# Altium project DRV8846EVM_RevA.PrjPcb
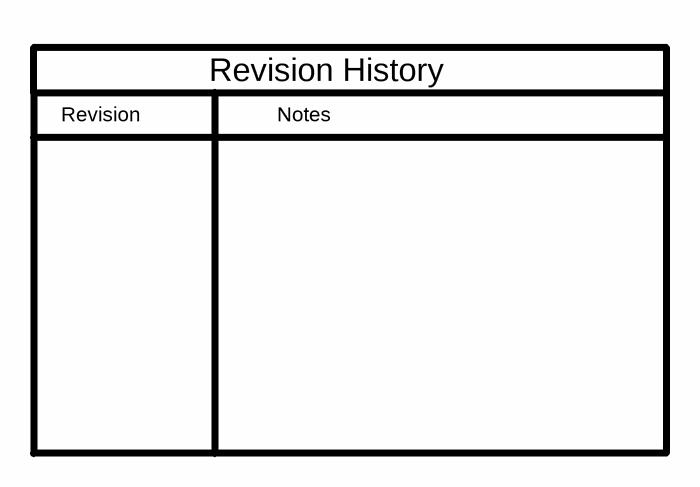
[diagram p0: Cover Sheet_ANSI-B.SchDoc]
TechSupport: http://www.ti.com/support; SCH_Rev: A; PRJ_Title: DRV8846EVM; PRJ_Number: DRV8846EVM; PRJ_Engineer: Rick Duncan; PRJ_Customer: Public Release; PCB_Rev: Rev A; PCB_Layout: Rick Duncan; CopyrightYear: 2014
4 sheets, 52 parts. Net scope: global (net labels, ports and power ports of the same name join across sheets).
Board file: DRV8846EVM_RevA.PcbDoc
Sheets:
  Cover Sheet_ANSI-B.SchDoc
  DRV8846EVM_RevA.SchDoc
  Hardware_ANSI-B.SchDoc
  DRV8846EVM_MSP430F2617_RevA.SchDoc

## Sheet Cover Sheet_ANSI-B.SchDoc
size 431 x 279 mm; Date: Not shown in title block; ApprovedBy: Not shown in title block; CheckedBy: Not shown in title block; Author: Not shown in title block; CompanyName: Not shown in title block; Engineer: Not shown in title block; Organization: Not shown in title block; Address1: Not shown in title block; Address2: Not shown in title block; Address3: Not shown in title block; Address4: Not shown in title block; DocumentNumber: 1; Revision: Use project parameter SCH_Rev; SheetNumber: 1; SheetTotal: 1; PageSetup: Record=PageOptions|CenterHorizontal=True|CenterVertical=True|PrintScale=1.00|XCorrection=1.00|YCorrection=1.00|PrintKind=0|BorderSize=5000000|LeftOffset=0|BottomOffset=0|Orientation=2|PaperLength=1000|PaperWidth=1000|Scale=100|PaperSource=15|PrintQuality=600|MediaType=1|DitherType=10|PaperKind=Letter|PrintScaleMode=1

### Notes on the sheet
- Revision
- Notes
- Revision History

## Sheet DRV8846EVM_RevA.SchDoc
size 431 x 279 mm; Date: Not shown in title block; ApprovedBy: Not shown in title block; CheckedBy: Not shown in title block; Author: Not shown in title block; CompanyName: Not shown in title block; Engineer: Not shown in title block; Organization: Not shown in title block; Address1: Not shown in title block; Address2: Not shown in title block; Address3: Not shown in title block; Address4: Not shown in title block; DocumentNumber: 1; Revision: Use project parameter SCH_Rev; SheetNumber: 1; SheetTotal: 1; PageSetup: Record=PageOptions|CenterHorizontal=True|CenterVertical=True|PrintScale=1.00|XCorrection=1.00|YCorrection=1.00|PrintKind=0|BorderSize=5000000|LeftOffset=0|BottomOffset=0|Orientation=2|PaperLength=1000|PaperWidth=1000|Scale=100|PaperSource=15|PrintQuality=600|MediaType=1|DitherType=10|PaperKind=Letter|PrintScaleMode=1
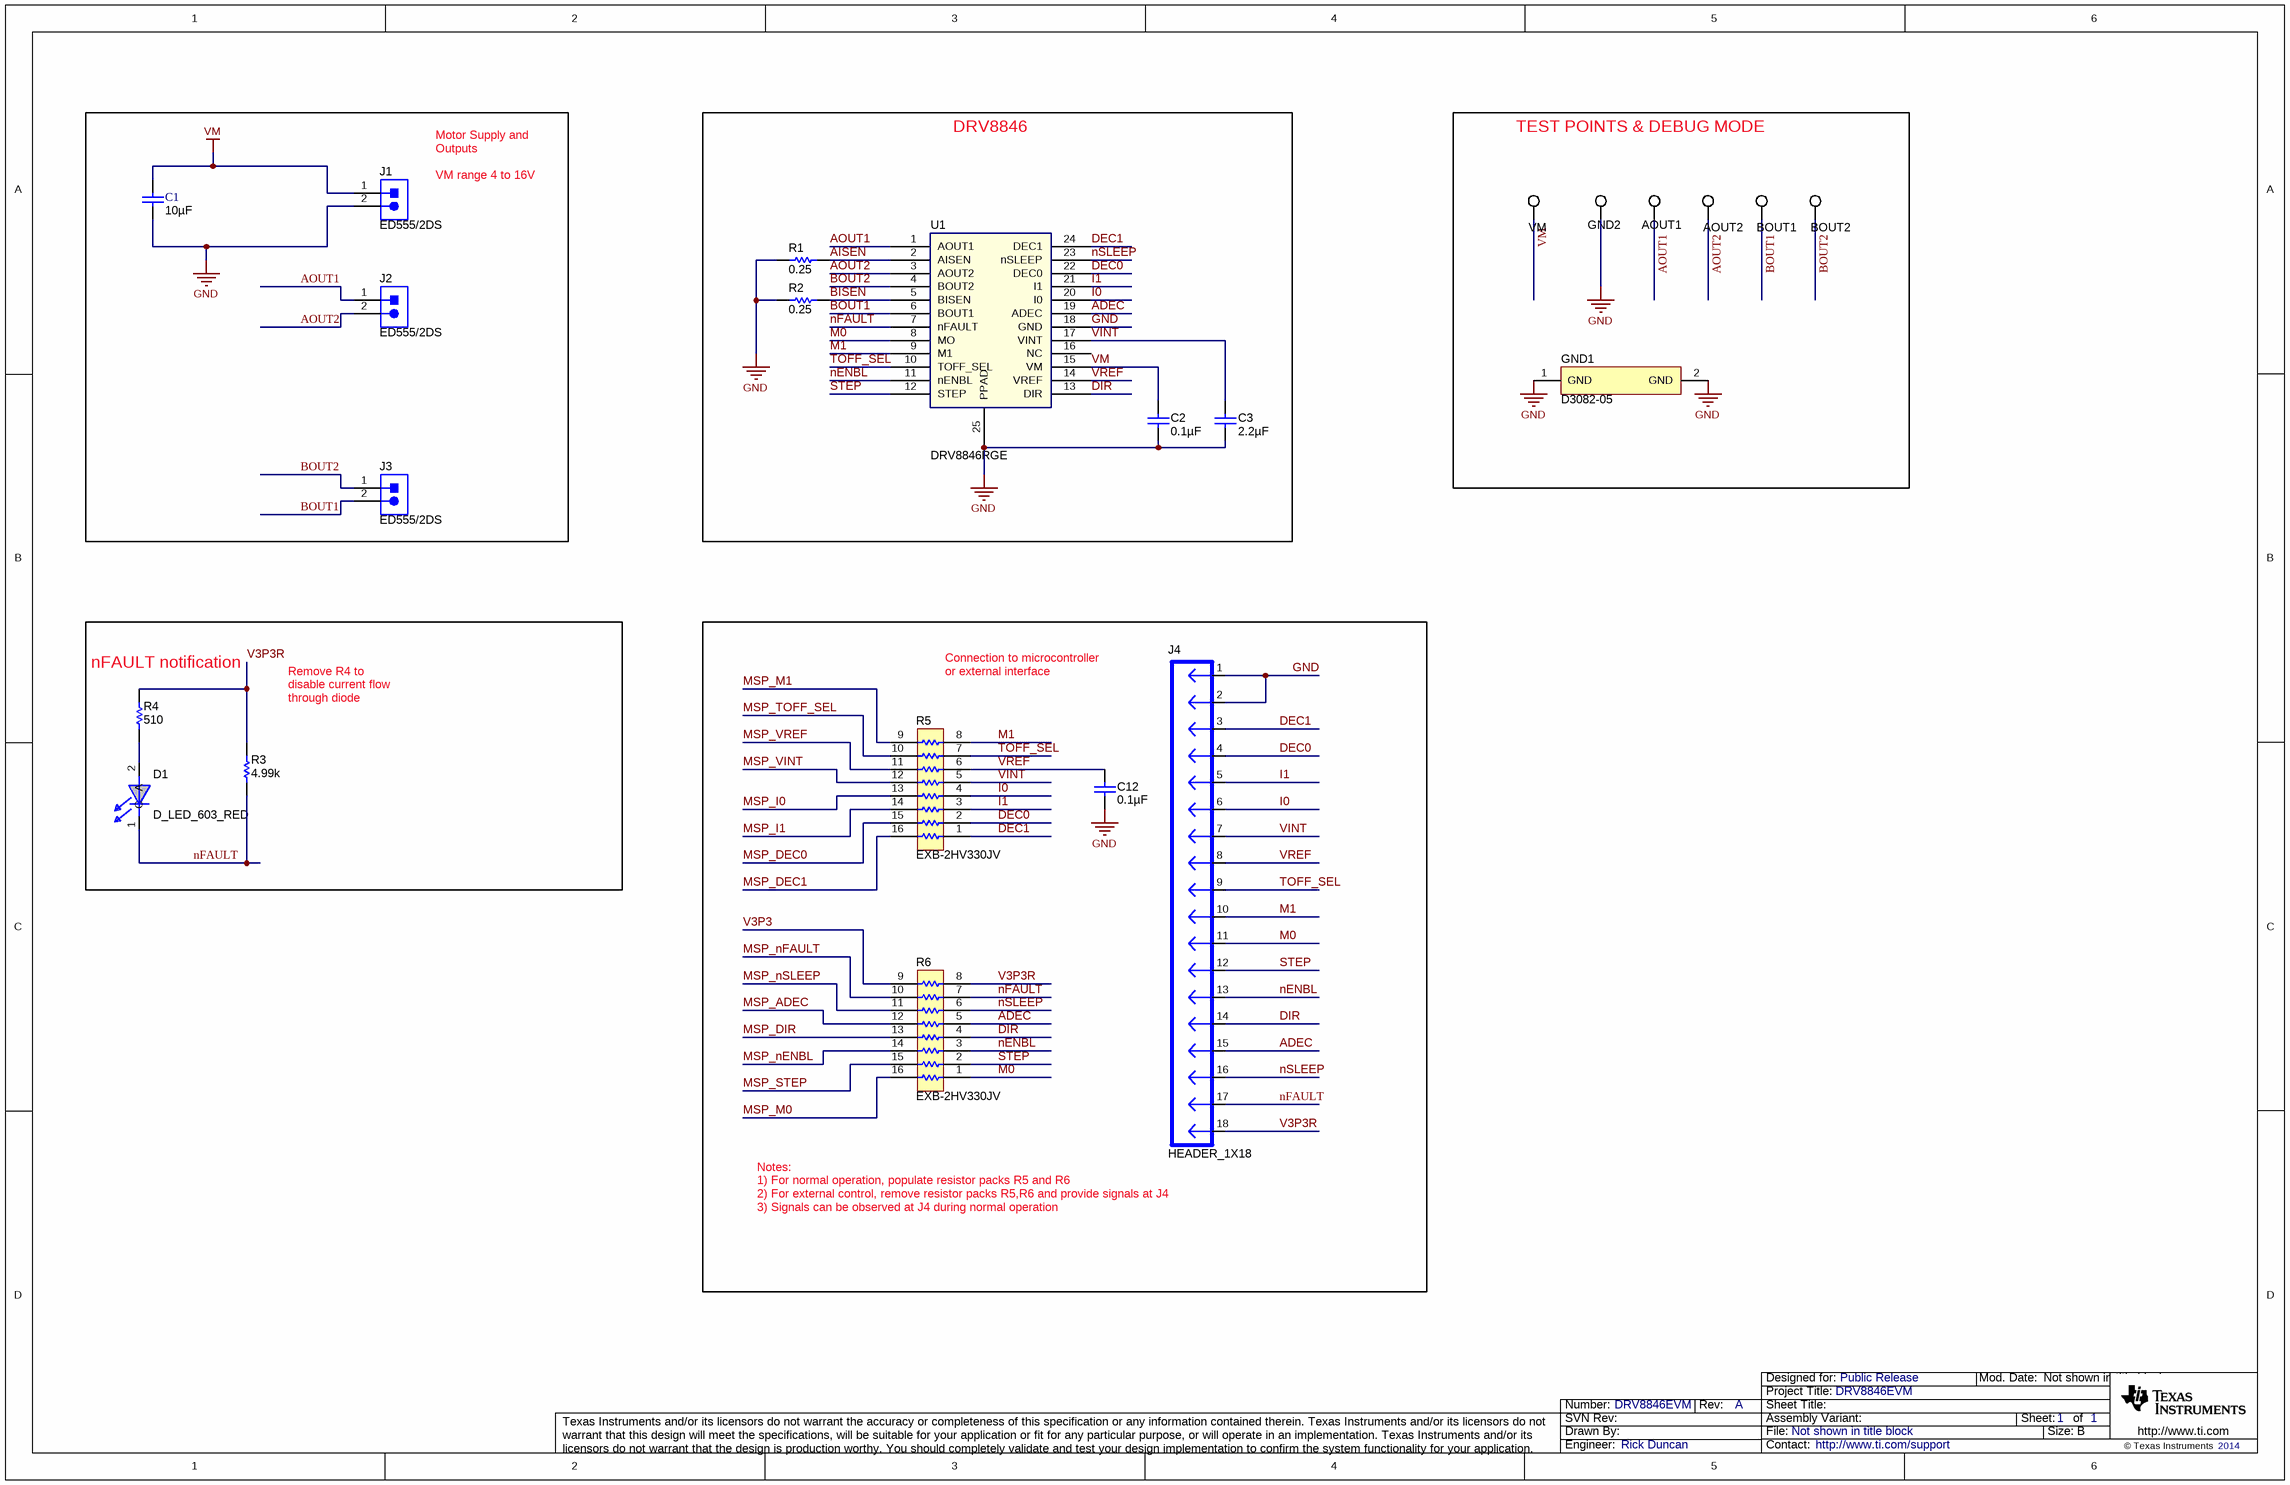
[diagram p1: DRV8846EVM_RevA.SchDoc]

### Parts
AOUT1  5016  [Testpoint_Keystone_Compact]  (value not drawn)
AOUT2  5016  [Testpoint_Keystone_Compact]  (value not drawn)
BOUT1  5016  [Testpoint_Keystone_Compact]  (value not drawn)
BOUT2  5016  [Testpoint_Keystone_Compact]  (value not drawn)
C1  ValueDisplayed: 10µF  [1210L]  (hidden comment: GMK325AB7106MM-T)
C2  ValueDisplayed: 0.1µF  [0603L]  (hidden comment: 06035C104KAT2A)
C3  ValueDisplayed: 2.2µF  [0402L]  (hidden comment: C1005X5R1E225K050BC)
C12  ValueDisplayed: 0.1µF  [0402L]  (hidden comment: C1005X5R0J104K)
D1  D_LED_603_RED  [LED603]
GND1  D3082-05  [GND_BRIDGE]
GND2  5016  [Testpoint_Keystone_Compact]  (value not drawn)
J1  ED555/2DS  [TERM_BLK_ED555-2DS]
J2  ED555/2DS  [TERM_BLK_ED555-2DS]
J3  ED555/2DS  [TERM_BLK_ED555-2DS]
J4  HEADER_1X18  [HEADER_1X18]
R1  value 0.25  [2010L]  (hidden comment: CSRN2010FKR250)
R2  value 0.25  [2010L]  (hidden comment: CSRN2010FKR250)
R3  value 4.99k  [0402L]  (hidden comment: CRCW04024K99FKED)
R4  value 510  [0402L]  (hidden comment: CRCW0402510RJNED)
R5  EXB-2HV330JV  [RESCAXS_EXB-2HV]
R6  EXB-2HV330JV  [RESCAXS_EXB-2HV]
U1  DRV8846RGE  [RGE0024H_MDBU]
VM  5016  [Testpoint_Keystone_Compact]  (value not drawn)

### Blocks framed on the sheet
DRV8846: C2 C3 R1 R2 U1
TEST POINTS & DEBUG MODE: AOUT1 AOUT2 BOUT1 BOUT2 GND1 GND2 VM
nFAULT notification: D1 R3 R4

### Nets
GND: C1.2 C2.2 C3.2 C12.2 GND1.1(GND) GND1.2(GND) GND2.1 J1.2 J4.1 J4.2 R1.1 R2.1 U1.18(GND) U1.25(PPAD)
V3P3: R6.9
VM: C1.1 C2.1 J1.1 U1.15(VM) VM.1
ADEC: J4.15 R6.5 U1.19(ADEC)
AISEN: R1.2 U1.2(AISEN)
AOUT1: AOUT1.1 J2.1 U1.1(AOUT1)
AOUT2: AOUT2.1 J2.2 U1.3(AOUT2)
BISEN: R2.2 U1.5(BISEN)
BOUT1: BOUT1.1 J3.2 U1.6(BOUT1)
BOUT2: BOUT2.1 J3.1 U1.4(BOUT2)
DEC0: J4.4 R5.2 U1.22(DEC0)
DEC1: J4.3 R5.1 U1.24(DEC1)
DIR: J4.14 R6.4 U1.13(DIR)
I0: J4.6 R5.4 U1.20(I0)
I1: J4.5 R5.3 U1.21(I1)
M0: J4.11 R6.1 U1.8(MO)
M1: J4.10 R5.8 U1.9(M1)
MSP_ADEC: R6.12
MSP_DEC0: R5.15
MSP_DEC1: R5.16
MSP_DIR: R6.13
MSP_I0: R5.13
MSP_I1: R5.14
MSP_M0: R6.16
MSP_M1: R5.9
MSP_nENBL: R6.14
MSP_nFAULT: R6.10
MSP_nSLEEP: R6.11
MSP_STEP: R6.15
MSP_TOFF_SEL: R5.10
MSP_VINT: R5.12
MSP_VREF: R5.11
nENBL: J4.13 R6.3 U1.11(nENBL)
nFAULT: D1.1(C) J4.17 R3.1 R6.7 U1.7(nFAULT)
nSLEEP: J4.16 R6.6 U1.23(nSLEEP)
STEP: J4.12 R6.2 U1.12(STEP)
TOFF_SEL: J4.9 R5.7 U1.10(TOFF_SEL)
V3P3R: J4.18 R3.2 R4.2 R6.8
VINT: C3.1 J4.7 R5.5 U1.17(VINT)
VREF: C12.1 J4.8 R5.6 U1.14(VREF)
NetD1_2: D1.2(A) R4.1

Not connected (* = marked no-connect by the designer): U1 16(NC)

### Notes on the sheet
- Motor Supply and Outputs
  VM range 4 to 16V
- Connection to microcontroller
  or external interface
- Remove R4 to disable current flow through diode
- (near J4) Notes:
  1) For normal operation, populate resistor packs R5 and R6
  2) For external control, remove resistor packs R5,R6 and provide signals at J4
  3) Signals can be observed at J4 during normal operation

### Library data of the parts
AOUT1 AOUT2 BOUT1 BOUT2 GND2 VM = 5016: Test Point, Compact, SMT; Manufacturer: Keystone; CompType: Test Point Loop; U/M: EA
C1 = GMK325AB7106MM-T: CAP, CERM, 10uF, 35V, +/-20%, X7R, 1210; Manufacturer: Taiyo Yuden; Polarized: N; CompType: Capacitor; U/M: EA; Cap_F: 0.00001; Tolerance_%: 20; Value1: Unknown; VDC_V: 35; TaMin_C: -55; TaMax_C: 125; Cap_Case: 1210
C2 = 06035C104KAT2A: CAP, CERM, 0.1uF, 50V, +/-10%, X7R, 0603; Manufacturer: AVX; Polarized: N; CompType: Capacitor; U/M: EA; Cap_F: 0.0000001; Tolerance_%: 10; Value1: Unknown; VDC_V: 50; TaMin_C: -55; TaMax_C: 125; Cap_Case: 0603
C3 = C1005X5R1E225K050BC: CAP, CERM, 2.2uF, 25V, +/-10%, X5R, 0402; Manufacturer: TDK; Polarized: N; CompType: Capacitor; U/M: EA; Cap_F: 0.0000022; Tolerance_%: 10; Value1: Unknown; VDC_V: 25; TaMin_C: -55; TaMax_C: 85; Cap_Case: 0402
C12 = C1005X5R0J104K: CAP, CERM, 0.1uF, 6.3V, +/-10%, X5R, 0402; Manufacturer: TDK; Polarized: N; CompType: Capacitor; U/M: EA; Cap_F: 0.0000001; Tolerance_%: 10; ESR_Ohm: 0.0186; Value1: 0.0186 ohm; VDC_V: 6.3; TaMin_C: -55; TaMax_C: 85; Cap_Case: 0402
D1 = D_LED_603_RED: Diode, LED, Red, 2.1-V, 20-mA, 6-mcd; PartNumber: LTST-C190CKT; Manufacturer: Lite On; Area: 9451; Value: LTST-C190CKT
GND1 = GND_Bridge: Manufacturer: Harwin; SymbolVersion: use current date i.e. 2008-05-20; SymbolCreator: Use a-id; CompType: Used in some BOM reports.  Useful for finding later.; U/M: EA, IN, or GM; Descriptiion: 1mm uninsulated shorting plug
J1-J3 = ED555/2DS: Terminal Block, 6A, 3.5mm Pitch, 2-Pos, TH; Manufacturer: On-Shore Technology; SymbolCreator: a0412235; CompType: Connector; U/M: EA
J4 = HEADER_1X18: Header, Male 18-pin, 100mil spacing,; Manufacturer: STD; PartNumber: PEC18SAAN; area: 198000; Value: PEC18SAAN
R1 R2 = CSRN2010FKR250: RES, 0.25 ohm, 1%, 1W, 2010; Manufacturer: Stackpole Electronics Inc; CompType: Resistor; Value_Code: R250; Tolerance_%: 1; TempCo: 250 ppm/C; U/M: EA
R3 = CRCW04024K99FKED: RES, 4.99k ohm, 1%, 0.063W, 0402; Manufacturer: Vishay-Dale; CompType: Resistor; Res_ohm: 4990; Value_Code: 4k99; Tolerance_%: 1; Power_W: 0.063; VDC_V: 50; TempCo: 100 ppm/C; EIA_Code: E96; U/M: EA
R4 = CRCW0402510RJNED: RES, 510 ohm, 5%, 0.063W, 0402; Manufacturer: Vishay-Dale; CompType: Resistor; Value_Code: 510R; Tolerance_%: 5; Power_W: 0.063; VDC_V: 50; TempCo: 200 ppm/C; EIA_Code: E24; U/M: EA
R5 R6 = EXB-2HV330JV: RES, 33 ohm, 5%, 0.0625W, Resistor Array - 8x1; Manufacturer: Panasonic; SymbolCreator: a0411947; Res_ohm: 33; Value: 33; Value_Code: 33R0; Tolerance_%: 5; Power_W: 0.0625; TempCo: 200 ppm/C; EIA_Code: E24; U/M: EA
U1 = DRV8846_2_RGE: Manufacturer: Texas Instruments; SymbolCreator: a0271951; CompType: Used in some BOM reports.  Useful for finding later.; U/M: EA, IN, or GM; Description: Stepper Motor Controller

## Sheet Hardware_ANSI-B.SchDoc
size 431 x 279 mm; Date: Not shown in title block; ApprovedBy: Not shown in title block; CheckedBy: Not shown in title block; Author: Not shown in title block; CompanyName: Not shown in title block; Engineer: Not shown in title block; Organization: Not shown in title block; Address1: Not shown in title block; Address2: Not shown in title block; Address3: Not shown in title block; Address4: Not shown in title block; DocumentNumber: 1; Revision: Use project parameter SCH_Rev; SheetNumber: 1; SheetTotal: 1; PageSetup: Record=PageOptions|CenterHorizontal=True|CenterVertical=True|PrintScale=1.00|XCorrection=1.00|YCorrection=1.00|PrintKind=0|BorderSize=5000000|LeftOffset=0|BottomOffset=0|Orientation=2|PaperLength=1000|PaperWidth=1000|Scale=100|PaperSource=15|PrintQuality=600|MediaType=1|DitherType=10|PaperKind=Letter|PrintScaleMode=1
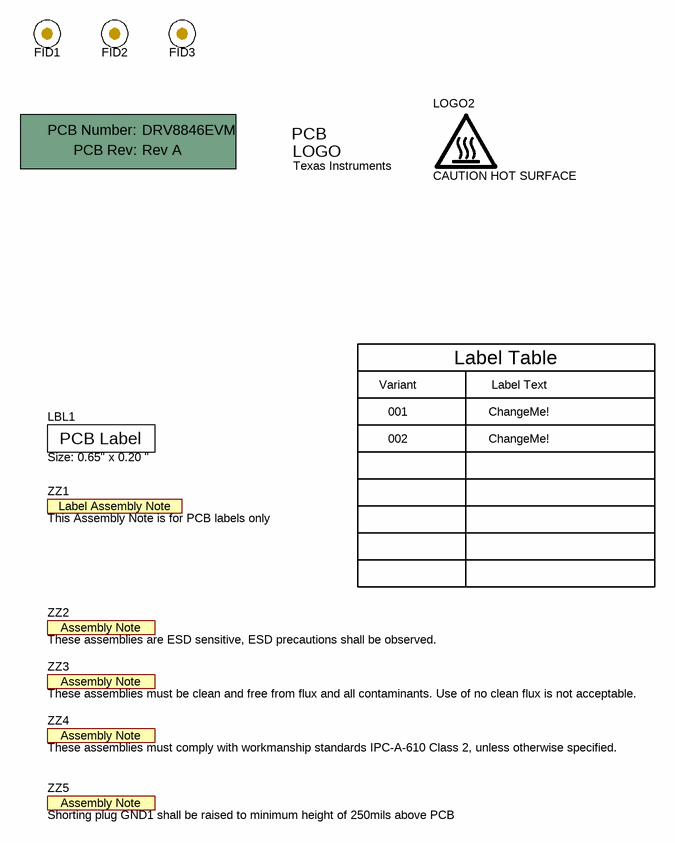
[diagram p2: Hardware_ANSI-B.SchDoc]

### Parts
!PCB  Printed Circuit Board  (value not drawn)  (mechanical)
FID1  Fiducial  [Fiducial10-20]  (value not drawn)
FID2  Fiducial  [Fiducial10-20]  (value not drawn)
FID3  Fiducial  [Fiducial10-20]  (value not drawn)
LBL1  Size: 0.65" x 0.20 "  [Label_650x200]
Logo1  Texas Instruments  [TI_Stacked_Overlay_Small]  (no BOM)
LOGO2  CAUTION HOT SURFACE  [IEC_HotSurface_Small]  (no BOM)
ZZ1  This Assembly Note is for PCB labels only  [AssemblyNoteLabel]  (no BOM)
ZZ2  These assemblies are ESD sensitive, ESD precautions shall be observed.  [AssemblyNote]  (no BOM)
ZZ3  These assemblies must be clean and free from flux and all contaminants. Use of no clean flux is not acceptable.  [AssemblyNote]  (no BOM)
ZZ4  These assemblies must comply with workmanship standards IPC-A-610 Class 2, unless otherwise specified.  [AssemblyNote]  (no BOM)
ZZ5  Shorting plug GND1 shall be raised to minimum height of 250mils above PCB  [AssemblyNote]  (no BOM)

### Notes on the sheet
- Label Table
- Variant
- 001
- 002
- Label Text
- ChangeMe!

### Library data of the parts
!PCB = PCB: Manufacturer: Any; PartNumber: DRV8846EVM; SymbolCreator: a0412235
FID1-FID3 = Fiducial: Fiducial mark.  There is nothing to buy or mount.; SymbolCreator: codlsc
LBL1 = THT-14-423-10: Thermal Transfer Printable Labels, 0.650" W x 0.200" H - 10,000 per roll; Manufacturer: Brady; SymbolCreator: a0412235; CompType: Label
Logo1 = TI_Logo: Texas Instrument Corporate Signature; SymbolCreator: codlsc
LOGO2 = IEC_HotSurface: IEC 61010-1 Hot Surface Warning; SymbolCreator: a0412235
ZZ1 = AssemblyNoteLabel: SymbolCreator: a0412235
ZZ2-ZZ5 = AssemblyNote: SymbolCreator: codlsc

## Sheet DRV8846EVM_MSP430F2617_RevA.SchDoc
size 431 x 279 mm; Date: Not shown in title block; ApprovedBy: Not shown in title block; CheckedBy: Not shown in title block; Author: Not shown in title block; CompanyName: Not shown in title block; Engineer: Not shown in title block; Organization: Not shown in title block; Address1: Not shown in title block; Address2: Not shown in title block; Address3: Not shown in title block; Address4: Not shown in title block; DocumentNumber: 1; Revision: Use project parameter SCH_Rev; SheetNumber: 1; SheetTotal: 1; PageSetup: Record=PageOptions|CenterHorizontal=True|CenterVertical=True|PrintScale=1.00|XCorrection=1.00|YCorrection=1.00|PrintKind=0|BorderSize=5000000|LeftOffset=0|BottomOffset=0|Orientation=2|PaperLength=1000|PaperWidth=1000|Scale=100|PaperSource=15|PrintQuality=600|MediaType=1|DitherType=10|PaperKind=Letter|PrintScaleMode=1
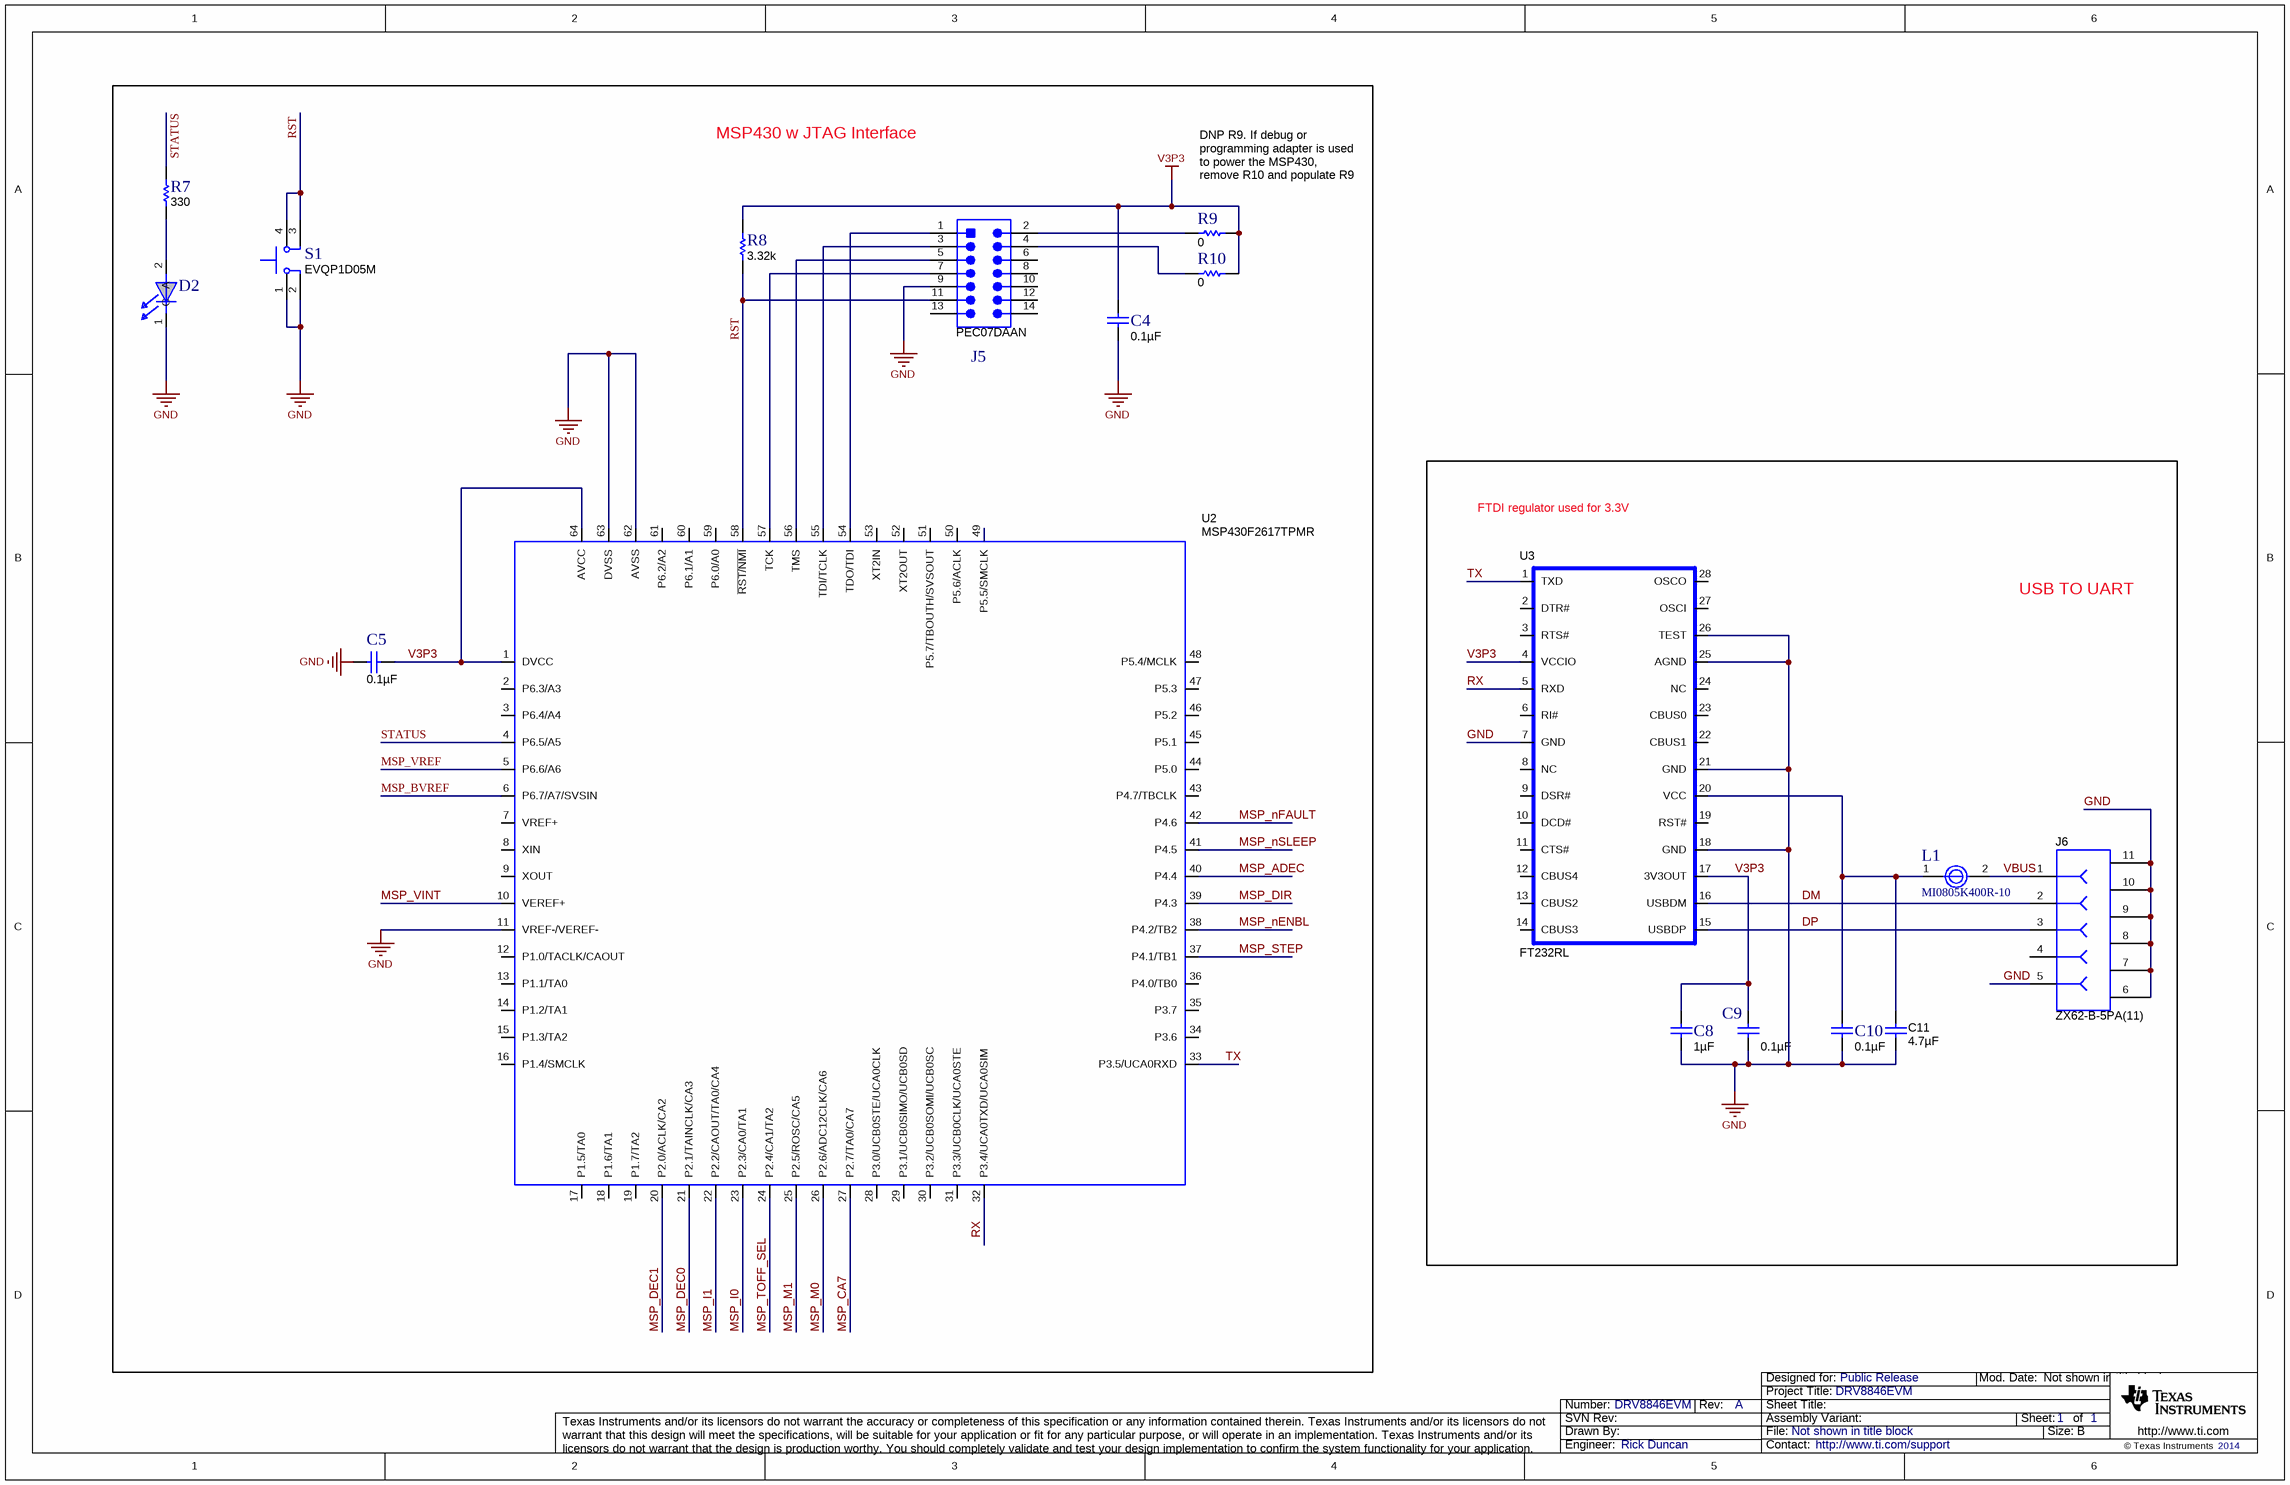
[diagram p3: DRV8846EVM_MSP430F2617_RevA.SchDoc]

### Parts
C4  ValueDisplayed: 0.1µF  [0402L]  (hidden comment: GRM155R61A104KA01D)
C5  ValueDisplayed: 0.1µF  [0402L]  (hidden comment: GRM155R61A104KA01D)
C8  ValueDisplayed: 1µF  [0402L]  (hidden comment: GRM155R61A105KE15D)
C9  ValueDisplayed: 0.1µF  [0402L]  (hidden comment: GRM155R61A104KA01D)
C10  ValueDisplayed: 0.1µF  [0402L]  (hidden comment: GRM155R61A104KA01D)
C11  ValueDisplayed: 4.7µF  [0603L]  (hidden comment: CGB3B1X5R1A475K055AC)
D2  LTST-C190GKT  [LED603]  (value not drawn)
J5  PEC07DAAN  [CONN_PEC07DAAN]
J6  ZX62-B-5PA(11)  [CONN_USB_micro_ZX62-B-5PA]
L1  MI0805K400R-10  [0805-IND]
R7  value 330  [0402L]  (hidden comment: CRCW0402330RJNED)
R8  value 3.32k  [0402L]  (hidden comment: CRCW04023K32FKED)
R9  value 0  [0402L]  (hidden comment: ERJ-2GE0R00X)
R10  value 0  [0402L]  (hidden comment: ERJ-2GE0R00X)
S1  EVQP1D05M  [SW_EVQxxx05M]
U2  MSP430F2617TPMR  [PM_S-PQFP-G64]
U3  FT232RL  [SSOP28]

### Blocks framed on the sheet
MSP430 w JTAG Interface: C4 C5 D2 J5 R7-R10 S1 U2
USB TO UART: C8-C11 J6 L1 U3

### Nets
GND: C4.2 C5.2 C8.2 C9.2 C10.2 C11.2 D2.1(C) J5.9 J6.5 J6.6 J6.7 J6.8 J6.9 J6.10 J6.11 S1.1 S1.2 U2.11(VREF-/VEREF-) U2.62(AVSS) U2.63(DVSS) U3.7(GND) U3.18(GND) U3.21(GND) U3.25(AGND) U3.26(TEST)
V3P3: C4.1 C5.1 C8.1 C9.1 R8.2 R9.1 R10.1 U2.1(DVCC) U2.64(AVCC) U3.4(VCCIO) U3.17(3V3OUT)
DM: J6.2 U3.16(USBDM)
DP: J6.3 U3.15(USBDP)
MSP_ADEC: U2.40(P4.4)
MSP_BVREF: U2.6(P6.7/A7/SVSIN)
MSP_CA7: U2.27(P2.7/TA0/CA7)
MSP_DEC0: U2.21(P2.1/TAINCLK/CA3)
MSP_DEC1: U2.20(P2.0/ACLK/CA2)
MSP_DIR: U2.39(P4.3)
MSP_I0: U2.23(P2.3/CA0/TA1)
MSP_I1: U2.22(P2.2/CAOUT/TA0/CA4)
MSP_M0: U2.26(P2.6/ADC12CLK/CA6)
MSP_M1: U2.25(P2.5/ROSC/CA5)
MSP_nENBL: U2.38(P4.2/TB2)
MSP_nFAULT: U2.42(P4.6)
MSP_nSLEEP: U2.41(P4.5)
MSP_STEP: U2.37(P4.1/TB1)
MSP_TOFF_SEL: U2.24(P2.4/CA1/TA2)
MSP_VINT: U2.10(VEREF+)
MSP_VREF: U2.5(P6.6/A6)
RST: J5.11 R8.1 S1.3 S1.4 U2.58(~{RST/NMI})
RX: U2.32(P3.4/UCA0TXD/UCA0SIM) U3.5(RXD)
STATUS: R7.2 U2.4(P6.5/A5)
TX: U2.33(P3.5/UCA0RXD) U3.1(TXD)
VBUS: J6.1 L1.2
NetC10_1: C10.1 C11.1 L1.1 U3.20(VCC)
NetD2_2: D2.2(A) R7.1
NetJ5_1: J5.1 U2.54(TDO/TDI)
NetJ5_2: J5.2 R9.2
NetJ5_3: J5.3 U2.55(TDI/TCLK)
NetJ5_4: J5.4 R10.2
NetJ5_5: J5.5 U2.56(TMS)
NetJ5_7: J5.7 U2.57(TCK)

Not connected (* = marked no-connect by the designer): J5 6 8 10 12 13 14; J6 4; U2 2(P6.3/A3) 3(P6.4/A4) 7(VREF+) 8(XIN) 9(XOUT) 12(P1.0/TACLK/CAOUT) 13(P1.1/TA0) 14(P1.2/TA1) 15(P1.3/TA2) 16(P1.4/SMCLK) 17(P1.5/TA0) 18(P1.6/TA1) 19(P1.7/TA2) 28(P3.0/UCB0STE/UCA0CLK) 29(P3.1/UCB0SIMO/UCB0SD) 30(P3.2/UCB0SOMI/UCB0SC) 31(P3.3/UCB0CLK/UCA0STE) 34(P3.6) 35(P3.7) 36(P4.0/TB0) 43(P4.7/TBCLK) 44(P5.0) 45(P5.1) 46(P5.2) 47(P5.3) 48(P5.4/MCLK) 49(P5.5/SMCLK) 50(P5.6/ACLK) 51(P5.7/TBOUTH/SVSOUT) 52(XT2OUT) 53(XT2IN) 59(P6.0/A0) 60(P6.1/A1) 61(P6.2/A2); U3 2(DTR#) 3(RTS#) 6(RI#) 8(NC) 9(DSR#) 10(DCD#) 11(CTS#) 12(CBUS4) 13(CBUS2) 14(CBUS3) 19(RST#) 22(CBUS1) 23(CBUS0) 24(NC) 27(OSCI) 28(OSCO)

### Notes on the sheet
- (near R9) DNP R9. If debug or programming adapter is used to power the MSP430, remove R10 and populate R9
- FTDI regulator used for 3.3V

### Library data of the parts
C4 C5 C9 C10 = GRM155R61A104KA01D: CAP, CERM, 0.1uF, 10V, +/-10%, X5R, 0402; Manufacturer: MuRata; Polarized: N; CompType: Capacitor; U/M: EA; Cap_F: 0.0000001; Tolerance_%: 10; Value1: Unknown; TaMin_C: -55; TaMax_C: 85; Cap_Case: 0402
C8 = GRM155R61A105KE15D: CAP, CERM, 1uF, 10V, +/-10%, X5R, 0402; Manufacturer: MuRata; Polarized: N; CompType: Capacitor; U/M: EA; Cap_F: 0.000001; Tolerance_%: 10; Value1: Unknown; TaMin_C: -55; TaMax_C: 85; Cap_Case: 0402
C11 = CGB3B1X5R1A475K055AC: CAP, CERM, 4.7uF, 10V, +/-10%, X5R, 0603; Manufacturer: TDK; Polarized: N; CompType: Capacitor; U/M: EA; Cap_F: 0.0000047; Tolerance_%: 10; Value1: Unknown; TaMin_C: -55; TaMax_C: 85; Cap_Case: 0603
D2 = D_LED_603_GRN: Diode, LED, Green, 2.1-V, 20-mA, 6-mcd; Manufacturer: Lite On; Area: 9451
J5 = PEC07DAAN: Header, 100mil, 7x2, Tin plated, TH; Manufacturer: Sullins Connector Solutions; SymbolCreator: a0412235; U/M: EA
J6 = ZX62-B-5PA(11): Connector, micro USB Type B, Receptacle, R/A, SMD; Manufacturer: Hirose Electric Co. Ltd.; SymbolCreator: a0411947; U/M: EA
L1 = BEAD-MI0805K_SERIES: Bead, Ferrite, yymA; Manufacturer: Steward; Value: 10mH; Area: 17,1; Description: Bead, Ferrite, 1.5A, 40Ohm
R7 = CRCW0402330RJNED: RES, 330 ohm, 5%, 0.063W, 0402; Manufacturer: Vishay-Dale; CompType: Resistor; Value_Code: 330R; Tolerance_%: 5; Power_W: 0.063; VDC_V: 50; TempCo: 200 ppm/C; EIA_Code: E24; U/M: EA
R8 = CRCW04023K32FKED: RES, 3.32k ohm, 1%, 0.063W, 0402; Manufacturer: Vishay-Dale; CompType: Resistor; Res_ohm: 3320; Value_Code: 3k32; Tolerance_%: 1; Power_W: 0.063; VDC_V: 50; TempCo: 100 ppm/C; EIA_Code: E96; U/M: EA
R9 R10 = ERJ-2GE0R00X: RES, 0 ohm, 5%, 0.063W, 0402; Manufacturer: Panasonic; CompType: Resistor; Value_Code: 0000; Tolerance_%: 5; Power_W: 0.063; VDC_V: 50; TempCo: 600 ppm/C; EIA_Code: E24; U/M: EA
S1 = EVQP1D05M: Switch, Tactile, SPST-NO, 0.05A, 12V, SMT; Manufacturer: Panasonic; SymbolCreator: a0799628; VDC_V: 12; SwitchFunction: Off-Mom; PositionCount: 1; CurrentRating_mA: 50
U2 = MSP430F23XTPM: IC, Mixed Signal Microcontroller, xKB+256B Flash Memory, 1KB RAM; Manufacturer: TI; Alternate Manufacturer: None; Area: 304704; Value: MSP430F26xTPM
U3 = FT232RL: IC,  USB  UART; Manufacturer: Future Techonology Devices; Area: 170112

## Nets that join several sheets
GND: DRV8846EVM_RevA (14 pins), DRV8846EVM_MSP430F2617_RevA (25 pins)
V3P3: DRV8846EVM_RevA (R6.9), DRV8846EVM_MSP430F2617_RevA (11 pins)
MSP_ADEC: DRV8846EVM_RevA (R6.12), DRV8846EVM_MSP430F2617_RevA (U2.40)
MSP_DEC0: DRV8846EVM_RevA (R5.15), DRV8846EVM_MSP430F2617_RevA (U2.21)
MSP_DEC1: DRV8846EVM_RevA (R5.16), DRV8846EVM_MSP430F2617_RevA (U2.20)
MSP_DIR: DRV8846EVM_RevA (R6.13), DRV8846EVM_MSP430F2617_RevA (U2.39)
MSP_I0: DRV8846EVM_RevA (R5.13), DRV8846EVM_MSP430F2617_RevA (U2.23)
MSP_I1: DRV8846EVM_RevA (R5.14), DRV8846EVM_MSP430F2617_RevA (U2.22)
MSP_M0: DRV8846EVM_RevA (R6.16), DRV8846EVM_MSP430F2617_RevA (U2.26)
MSP_M1: DRV8846EVM_RevA (R5.9), DRV8846EVM_MSP430F2617_RevA (U2.25)
MSP_nENBL: DRV8846EVM_RevA (R6.14), DRV8846EVM_MSP430F2617_RevA (U2.38)
MSP_nFAULT: DRV8846EVM_RevA (R6.10), DRV8846EVM_MSP430F2617_RevA (U2.42)
MSP_nSLEEP: DRV8846EVM_RevA (R6.11), DRV8846EVM_MSP430F2617_RevA (U2.41)
MSP_STEP: DRV8846EVM_RevA (R6.15), DRV8846EVM_MSP430F2617_RevA (U2.37)
MSP_TOFF_SEL: DRV8846EVM_RevA (R5.10), DRV8846EVM_MSP430F2617_RevA (U2.24)
MSP_VINT: DRV8846EVM_RevA (R5.12), DRV8846EVM_MSP430F2617_RevA (U2.10)
MSP_VREF: DRV8846EVM_RevA (R5.11), DRV8846EVM_MSP430F2617_RevA (U2.5)

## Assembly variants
001: not fitted FID1 FID2 FID3 R9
